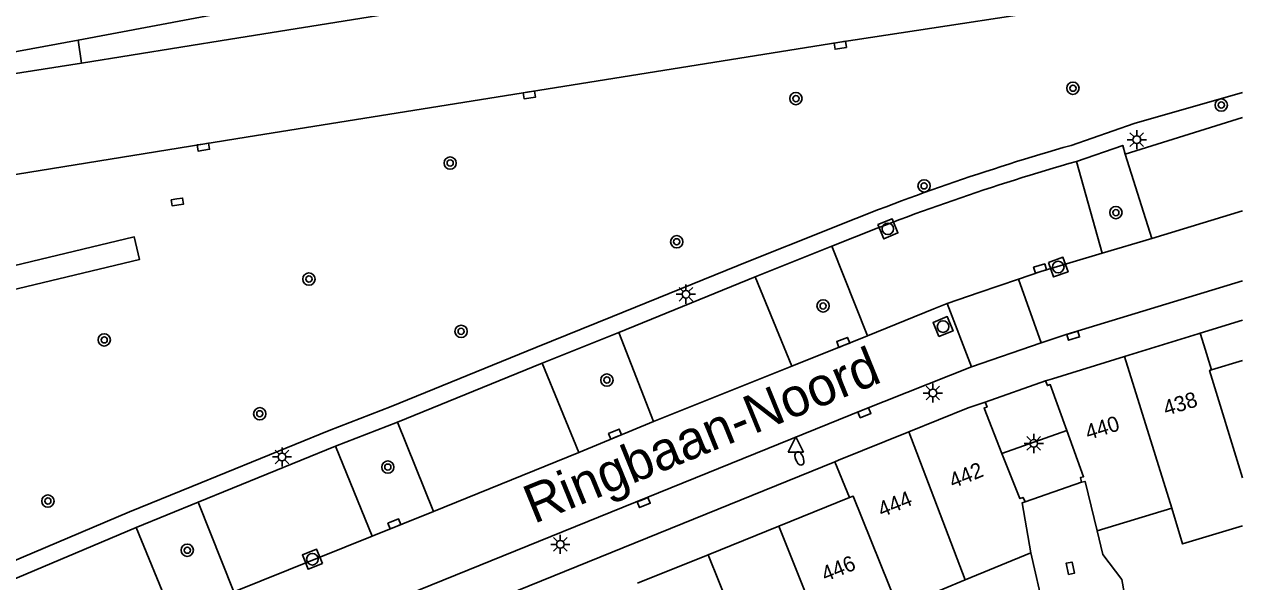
# Model space of a CAD drawing. Extents: x 132573 to 132944, y 398226 to 398676.
# Drawn here: x 132860.9 to 132940.1, y 398548.2 to 398584.5 of the extents above; entities that cross this region are included whole.
import ezdxf

# ---------------------------------------------------------------- set-up
doc = ezdxf.new("R2010")
doc.units = 0
for name, color, linetype in [('gg-afsc-muur', 7, 'Continuous'), ('gg-anno-huisnummerreeks BGT', 7, 'Continuous'), ('gg-anno-openbare ruimte label', 7, 'Continuous'), ('gg-bbg-gedigitaliseerde bebouwing', 7, 'Continuous'), ('gg-bbg-hoofdgebouw', 7, 'Continuous'), ('gg-bbg-onder overbouw', 7, 'Continuous'), ('gg-bbg-pand overbouw', 7, 'Continuous'), ('gg-bbg-tussenscheiding', 7, 'Continuous'), ('gg-bbg-tussenscheiding niveau 01', 7, 'Continuous'), ('gg-knt-verharding', 7, 'Continuous'), ('gg-knt-verharding nz', 7, 'Continuous'), ('gt-grn-groengrens', 7, 'Continuous'), ('gt-symb-boom', 7, 'Continuous'), ('gt-symb-brandkraan', 7, 'Continuous'), ('gt-symb-kolk', 7, 'Continuous'), ('gt-symb-kolk center center', 7, 'Continuous'), ('gt-symb-lichtmast', 7, 'Continuous'), ('gt-symb-rioolschacht', 7, 'Continuous'), ('gt-symb-waterafsluiter', 7, 'Continuous')]:
    doc.layers.add(name, color=color, linetype=linetype)

msp = doc.modelspace()

# ---------------------------------------------------------------- linework, layer by layer
at = {"layer": 'gg-afsc-muur'}
msp.add_line((132929.03, 398538.312), (132926.35, 398550.101), dxfattribs=at)
msp.add_lwpolyline([(132933.193, 398543.17), (132932.27, 398548.361), (132931.02, 398549.991), (132930.646, 398551.538)], dxfattribs=at)
at = {"layer": 'gg-bbg-gedigitaliseerde bebouwing'}
msp.add_line((132930.646, 398551.538), (132935.504, 398553.01), dxfattribs=at)
msp.add_lwpolyline([(132935.504, 398553.01), (132936.21, 398550.681), (132940.113, 398551.865)], dxfattribs=at)
at = {"layer": 'gg-bbg-hoofdgebouw'}
for p, q in [((132937.226, 398564.36), (132932.44, 398562.88)), ((132937.36, 398564.401), (132937.226, 398564.36)), ((132937.591, 398563.645), (132937.36, 398564.401)), ((132938.09, 398562.011), (132937.591, 398563.645)), ((132932.44, 398562.88), (132927.745, 398561.429)), ((132940.113, 398562.624), (132938.09, 398562.011)), ((132927.745, 398561.429), (132927.3, 398561.291)), ((132913.851, 398556.128), (132918.424, 398557.977)), ((132913.851, 398556.128), (132913.61, 398556.031)), ((132913.61, 398556.031), (132914.55, 398553.701)), ((132914.55, 398553.701), (132909.958, 398551.841)), ((132909.958, 398551.841), (132905.367, 398549.981)), ((132905.367, 398549.981), (132900.775, 398548.121)), ((132926.35, 398550.101), (132922.085, 398548.337)), ((132922.085, 398548.337), (132917.731, 398546.536))]:
    msp.add_line(p, q, dxfattribs=at)
for points in [[(132923.38, 398559.901), (132922.27, 398559.531), (132918.424, 398557.977)], [(132930.646, 398551.538), (132929.87, 398554.751), (132929.64, 398554.701)], [(132925.97, 398553.411), (132925.78, 398553.351), (132926.35, 398550.101)]]:
    msp.add_lwpolyline(points, dxfattribs=at)
at = {"layer": 'gg-bbg-onder overbouw'}
for points in [[(132927.3, 398561.291), (132927.42, 398560.981), (132927.61, 398561.051), (132928.69, 398558.051)], [(132924.47, 398556.576), (132923.3, 398559.521), (132923.5, 398559.601), (132923.38, 398559.901)], [(132928.69, 398558.051), (132929.77, 398555.051), (132929.57, 398555.001), (132929.64, 398554.701)], [(132925.97, 398553.411), (132925.84, 398553.711), (132925.64, 398553.631), (132924.47, 398556.576)]]:
    msp.add_lwpolyline(points, dxfattribs=at)
at = {"layer": 'gg-bbg-pand overbouw'}
for p, q in [((132923.38, 398559.901), (132927.3, 398561.291)), ((132925.97, 398553.411), (132929.64, 398554.701))]:
    msp.add_line(p, q, dxfattribs=at)
at = {"layer": 'gg-bbg-tussenscheiding'}
for p, q in [((132935.504, 398553.01), (132932.44, 398562.88)), ((132922.085, 398548.337), (132918.424, 398557.977)), ((132913.827, 398542.218), (132909.958, 398551.841)), ((132909.23, 398540.371), (132905.367, 398549.981))]:
    msp.add_line(p, q, dxfattribs=at)
for points in [[(132940.113, 398554.993), (132937.962, 398561.972), (132938.09, 398562.011)], [(132917.731, 398546.536), (132914.793, 398553.799), (132914.55, 398553.701)]]:
    msp.add_lwpolyline(points, dxfattribs=at)
at = {"layer": 'gg-bbg-tussenscheiding niveau 01'}
msp.add_line((132928.69, 398558.051), (132924.47, 398556.576), dxfattribs=at)
at = {"layer": 'gg-knt-verharding'}
for p, q in [((132864.634, 398581.957), (132874.309, 398583.511)), ((132864.406, 398583.453), (132854.757, 398581.671)), ((132864.634, 398581.957), (132864.406, 398583.453)), ((132932.48, 398576.046), (132940.113, 398578.414)), ((132929.323, 398575.569), (132930.989, 398569.6)), ((132934.206, 398570.557), (132932.48, 398576.046)), ((132915.737, 398564.23), (132913.417, 398570.047)), ((132930.989, 398569.6), (132934.206, 398570.557)), ((132899.552, 398564.446), (132908.426, 398568.067)), ((132908.426, 398568.067), (132910.808, 398562.241)), ((132927.026, 398563.755), (132925.541, 398567.896)), ((132920.914, 398566.317), (132922.48, 398562.197)), ((132937.36, 398564.401), (132940.113, 398565.236)), ((132901.816, 398558.646), (132899.552, 398564.446)), ((132910.808, 398562.241), (132915.737, 398564.23)), ((132927.026, 398563.755), (132922.48, 398562.197)), ((132885.165, 398558.608), (132894.581, 398562.449)), ((132894.581, 398562.449), (132896.959, 398556.625)), ((132887.504, 398552.792), (132885.165, 398558.608)), ((132896.959, 398556.625), (132901.816, 398558.646)), ((132872.221, 398553.404), (132881.143, 398557.039)), ((132881.143, 398557.039), (132883.53, 398551.178)), ((132913.61, 398556.031), (132886.06, 398544.851)), ((132874.532, 398547.556), (132872.221, 398553.404)), ((132883.53, 398551.178), (132887.504, 398552.792)), ((132859.304, 398548), (132868.18, 398551.756)), ((132868.18, 398551.756), (132870.582, 398545.942))]:
    msp.add_line(p, q, dxfattribs=at)
for points in [[(132874.309, 398583.511), (132916.485, 398590.284), (132940.113, 398594.048)], [(132906.418, 398590.682), (132883.092, 398586.984), (132874.206, 398585.298), (132864.406, 398583.453)], [(132875.328, 398577.144), (132913.921, 398583.321), (132932.161, 398586.131), (132940.113, 398587.424)], [(132833.719, 398575.867), (132834.722, 398576.148), (132839.572, 398577.354), (132849.354, 398579.386), (132858.236, 398580.967), (132864.634, 398581.957)], [(132850.137, 398572.989), (132851.351, 398573.263), (132872.519, 398576.694), (132875.328, 398577.144)], [(132940.113, 398567.792), (132928.64, 398564.304), (132927.026, 398563.755)], [(132922.48, 398562.197), (132915.452, 398559.401), (132869.443, 398540.745), (132862.897, 398537.875)]]:
    msp.add_lwpolyline(points, dxfattribs=at)
msp.add_arc((132970.525, 398431.218), 150.116, 105.93032, 112.36006, dxfattribs=at)
at = {"layer": 'gg-knt-verharding nz'}
for p, q in [((132940.113, 398572.36), (132934.206, 398570.557)), ((132901.816, 398558.646), (132910.808, 398562.241)), ((132887.504, 398552.792), (132896.959, 398556.625)), ((132874.532, 398547.556), (132883.53, 398551.178))]:
    msp.add_line(p, q, dxfattribs=at)
for points in [[(132930.989, 398569.6), (132926.999, 398568.409), (132925.541, 398567.896)], [(132925.541, 398567.896), (132922.979, 398567.047), (132920.914, 398566.317)], [(132920.914, 398566.317), (132920.035, 398565.977), (132915.737, 398564.23)]]:
    msp.add_lwpolyline(points, dxfattribs=at)
at = {"layer": 'gt-grn-groengrens'}
for p, q in [((132913.011, 398571.069), (132908.01, 398569.085)), ((132913.417, 398570.047), (132908.426, 398568.067)), ((132899.142, 398565.467), (132908.01, 398569.085)), ((132894.166, 398563.468), (132899.142, 398565.467)), ((132894.581, 398562.449), (132899.552, 398564.446)), ((132884.765, 398559.633), (132894.166, 398563.468)), ((132884.765, 398559.633), (132880.728, 398558.058)), ((132885.165, 398558.608), (132881.143, 398557.039)), ((132871.806, 398554.423), (132880.728, 398558.058)), ((132871.806, 398554.423), (132867.751, 398552.769)), ((132872.221, 398553.404), (132868.18, 398551.756)), ((132858.832, 398548.994), (132867.751, 398552.769))]:
    msp.add_line(p, q, dxfattribs=at)
for points in [[(132940.113, 398580.056), (132933.055, 398578.023), (132928.964, 398576.609)], [(132932.48, 398576.046), (132932.319, 398576.605), (132929.323, 398575.569)], [(132831.875, 398561.969), (132832.225, 398560.51), (132868.409, 398569.194), (132868.059, 398570.653), (132831.875, 398561.969)]]:
    msp.add_lwpolyline(points, dxfattribs=at)
msp.add_arc((132970.287, 398431.875), 150.517, 105.9347, 112.36647, dxfattribs=at)
at = {"layer": 'gt-symb-boom'}
for centre, radius in [((132929.082, 398580.329), 0.4), ((132929.082, 398580.329), 0.2), ((132911.074, 398579.652), 0.4), ((132911.074, 398579.652), 0.2), ((132938.726, 398579.235), 0.4), ((132938.726, 398579.235), 0.2), ((132888.597, 398575.46), 0.4), ((132888.597, 398575.46), 0.2), ((132919.406, 398573.976), 0.4), ((132919.406, 398573.976), 0.2), ((132931.872, 398572.236), 0.4), ((132931.872, 398572.236), 0.2), ((132903.323, 398570.339), 0.4), ((132903.323, 398570.339), 0.2), ((132879.419, 398567.914), 0.4), ((132879.419, 398567.914), 0.2), ((132912.843, 398566.165), 0.4), ((132912.843, 398566.165), 0.2), ((132889.311, 398564.512), 0.4), ((132889.311, 398564.512), 0.2), ((132866.107, 398563.957), 0.4), ((132866.107, 398563.957), 0.2), ((132898.785, 398561.343), 0.4), ((132898.785, 398561.343), 0.2), ((132876.219, 398559.151), 0.4), ((132876.219, 398559.151), 0.2), ((132884.545, 398555.682), 0.4), ((132884.545, 398555.682), 0.2), ((132862.448, 398553.472), 0.4), ((132862.448, 398553.472), 0.2), ((132871.508, 398550.273), 0.4), ((132871.508, 398550.273), 0.2)]:
    msp.add_circle(centre, radius, dxfattribs=at)
at = {"layer": 'gt-symb-brandkraan'}
for centre, radius, start, end in [((132911.217, 398556.475), 0.206, 38.23024, 183.09638), ((132909.022, 398554.746), 3, 37.55535, 38.23024), ((132910.657, 398556.003), 0.938, 3.77129, 37.55535), ((132914.007, 398556.626), 3, 183.09638, 183.77127), ((132911.949, 398556.491), 0.938, 183.77127, 217.55537), ((132913.584, 398557.748), 3, 217.55537, 218.23025), ((132911.389, 398556.019), 0.206, 218.23025, 3.09639), ((132908.599, 398555.868), 3, 3.09639, 3.77129)]:
    msp.add_arc(centre, radius, start, end, dxfattribs=at)
at = {"layer": 'gt-symb-kolk'}
for points in [[(132913.921, 398583.321), (132913.551, 398583.262), (132913.614, 398582.867), (132914.354, 398582.985), (132914.291, 398583.38), (132913.921, 398583.321)], [(132893.72, 398580.086), (132893.35, 398580.027), (132893.413, 398579.632), (132894.153, 398579.75), (132894.09, 398580.145), (132893.72, 398580.086)], [(132872.519, 398576.694), (132872.149, 398576.634), (132872.213, 398576.239), (132872.953, 398576.359), (132872.889, 398576.754), (132872.519, 398576.694)], [(132870.837, 398573.123), (132870.467, 398573.064), (132870.53, 398572.669), (132871.271, 398572.787), (132871.207, 398573.182), (132870.837, 398573.123)], [(132926.999, 398568.409), (132927.358, 398568.516), (132927.244, 398568.9), (132926.525, 398568.685), (132926.64, 398568.302), (132926.999, 398568.409)], [(132929.036, 398564.423), (132928.677, 398564.314), (132928.794, 398563.931), (132929.511, 398564.149), (132929.395, 398564.532), (132929.036, 398564.423)], [(132914.22, 398563.611), (132914.568, 398563.751), (132914.419, 398564.122), (132913.723, 398563.842), (132913.872, 398563.471), (132914.22, 398563.611)], [(132915.452, 398559.401), (132915.104, 398559.262), (132915.252, 398558.89), (132915.949, 398559.169), (132915.8, 398559.54), (132915.452, 398559.401)], [(132899.394, 398557.641), (132899.74, 398557.785), (132899.586, 398558.155), (132898.894, 398557.866), (132899.048, 398557.497), (132899.394, 398557.641)], [(132901.108, 398553.558), (132900.76, 398553.417), (132900.91, 398553.047), (132901.606, 398553.328), (132901.456, 398553.699), (132901.108, 398553.558)], [(132885.053, 398551.802), (132885.4, 398551.944), (132885.248, 398552.314), (132884.554, 398552.03), (132884.706, 398551.66), (132885.053, 398551.802)]]:
    msp.add_lwpolyline(points, dxfattribs=at)
at = {"layer": 'gt-symb-kolk center center'}
msp.add_lwpolyline([(132928.787, 398548.689), (132928.632, 398549.422), (132929.023, 398549.505), (132929.178, 398548.772)], close=True, dxfattribs=at)
at = {"layer": 'gt-symb-lichtmast'}
for p, q in [((132933.056, 398577.156), (132932.791, 398577.421)), ((132933.233, 398577.229), (132933.233, 398577.604)), ((132933.41, 398577.156), (132933.675, 398577.421)), ((132932.983, 398576.979), (132932.608, 398576.979)), ((132933.056, 398576.802), (132932.791, 398576.537)), ((132933.233, 398576.729), (132933.233, 398576.354)), ((132933.675, 398576.537), (132933.41, 398576.802)), ((132933.483, 398576.979), (132933.858, 398576.979)), ((132903.674, 398566.925), (132903.299, 398566.925)), ((132903.747, 398567.102), (132903.482, 398567.367)), ((132903.924, 398567.175), (132903.924, 398567.55)), ((132904.101, 398567.102), (132904.366, 398567.367)), ((132904.174, 398566.925), (132904.549, 398566.925)), ((132903.747, 398566.748), (132903.482, 398566.483)), ((132903.924, 398566.675), (132903.924, 398566.3)), ((132904.366, 398566.483), (132904.101, 398566.748)), ((132919.798, 398560.678), (132919.533, 398560.943)), ((132919.975, 398560.751), (132919.975, 398561.126)), ((132920.152, 398560.678), (132920.417, 398560.943)), ((132919.725, 398560.501), (132919.35, 398560.501)), ((132919.798, 398560.324), (132919.533, 398560.059)), ((132919.975, 398560.251), (132919.975, 398559.876)), ((132920.417, 398560.059), (132920.152, 398560.324)), ((132920.225, 398560.501), (132920.6, 398560.501)), ((132926.357, 398557.397), (132926.092, 398557.662)), ((132926.534, 398557.47), (132926.534, 398557.845)), ((132926.711, 398557.397), (132926.976, 398557.662)), ((132877.489, 398556.515), (132877.224, 398556.78)), ((132877.666, 398556.588), (132877.666, 398556.963)), ((132877.843, 398556.515), (132878.108, 398556.78)), ((132926.284, 398557.22), (132925.909, 398557.22)), ((132926.357, 398557.043), (132926.092, 398556.778)), ((132926.534, 398556.97), (132926.534, 398556.595)), ((132926.976, 398556.778), (132926.711, 398557.043)), ((132926.784, 398557.22), (132927.159, 398557.22)), ((132877.416, 398556.338), (132877.041, 398556.338)), ((132877.489, 398556.161), (132877.224, 398555.896)), ((132877.666, 398556.088), (132877.666, 398555.713)), ((132878.108, 398555.896), (132877.843, 398556.161)), ((132877.916, 398556.338), (132878.291, 398556.338)), ((132895.579, 398550.831), (132895.314, 398551.096)), ((132895.756, 398550.904), (132895.756, 398551.279)), ((132895.933, 398550.831), (132896.198, 398551.096)), ((132895.506, 398550.654), (132895.131, 398550.654)), ((132895.579, 398550.477), (132895.314, 398550.212)), ((132895.756, 398550.404), (132895.756, 398550.029)), ((132896.198, 398550.212), (132895.933, 398550.477)), ((132896.006, 398550.654), (132896.381, 398550.654))]:
    msp.add_line(p, q, dxfattribs=at)
for centre in [(132933.233, 398576.979), (132903.924, 398566.925), (132919.975, 398560.501), (132926.534, 398557.22), (132877.666, 398556.338), (132895.756, 398550.654)]:
    msp.add_circle(centre, 0.25, dxfattribs=at)
at = {"layer": 'gt-symb-rioolschacht'}
for points in [[(132916.397, 398571.452), (132916.779, 398570.528), (132917.703, 398570.91), (132917.321, 398571.834)], [(132927.489, 398569), (132927.819, 398568.056), (132928.763, 398568.386), (132928.433, 398569.33)], [(132920.362, 398564.17), (132921.29, 398564.544), (132920.916, 398565.472), (132919.988, 398565.098)], [(132880.29, 398549.41), (132879.917, 398550.337), (132878.99, 398549.964), (132879.363, 398549.037)]]:
    msp.add_lwpolyline(points, close=True, dxfattribs=at)
for centre in [(132917.05, 398571.181), (132928.126, 398568.693), (132920.639, 398564.821), (132879.64, 398549.687)]:
    msp.add_circle(centre, 0.375, dxfattribs=at)
at = {"layer": 'gt-symb-waterafsluiter'}
for p, q in [((132910.566, 398556.656), (132911.066, 398557.656)), ((132911.066, 398557.656), (132911.566, 398556.656)), ((132911.566, 398556.656), (132910.566, 398556.656))]:
    msp.add_line(p, q, dxfattribs=at)

# ---------------------------------------------------------------- texts
at = {"layer": 'gg-anno-huisnummerreeks BGT'}
for s, rotation, p in [('438', 17.2, (132935.135, 398559.003)), ('440', 17.2, (132930.069, 398557.436)), ('442', 22, (132921.282, 398554.277)), ('444', 22, (132916.654, 398552.407)), ('446', 22, (132912.982, 398548.211))]:
    msp.add_text(s, height=1, rotation=rotation, dxfattribs=at).set_placement(p)
at = {"layer": 'gg-anno-openbare ruimte label'}
msp.add_text('Ringbaan-Noord', height=2.5, rotation=22.2, dxfattribs=at).set_placement((132894.044, 398551.976))

doc.saveas('drawing.dxf')
